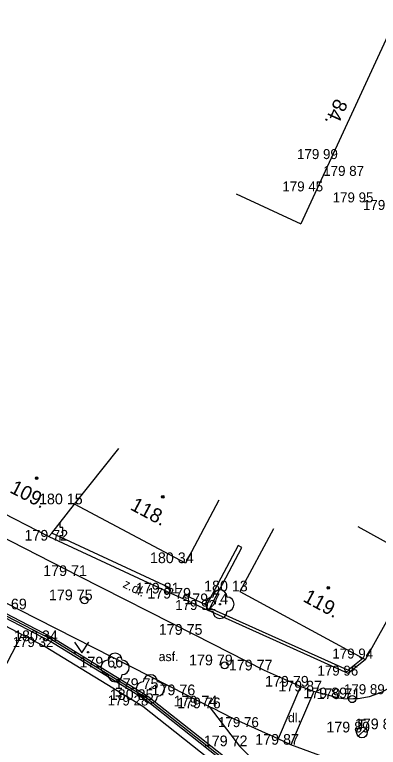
# Model space of a CAD drawing. Extents: x -537755 to -537431, y -1180722 to -1180510.
# Drawn here: x -537671.4 to -537645.9, y -1180566.9 to -1180515.4 of the extents above; entities that cross this region are included whole.
import ezdxf

# ---------------------------------------------------------------- set-up
doc = ezdxf.new("R2010")
doc.units = 0
for name, color, linetype in [('Vrstva 1', 7, 'Continuous'), ('Vrstva 10', 7, 'Continuous'), ('Vrstva 11', 7, 'Continuous'), ('Vrstva 15', 7, 'Continuous'), ('Vrstva 22', 7, 'Continuous'), ('Vrstva 24', 7, 'Continuous'), ('Vrstva 28', 7, 'Continuous'), ('Vrstva 3', 7, 'Continuous'), ('Vrstva 31', 7, 'Continuous'), ('Vrstva 36', 7, 'Continuous'), ('Vrstva 39', 7, 'Continuous'), ('Vrstva 40', 7, 'Continuous'), ('Vrstva 47', 7, 'Continuous'), ('Vrstva 5', 7, 'Continuous'), ('Vrstva 7', 7, 'Continuous'), ('Vrstva 8', 7, 'Continuous'), ('Vrstva 9', 7, 'Continuous')]:
    doc.layers.add(name, color=color, linetype=linetype)

msp = doc.modelspace()

# ---------------------------------------------------------------- linework, layer by layer
at = {"layer": 'Vrstva 1'}
for p, q in [((-537649.27, -1180525.57), (-537649.27, -1180525.57)), ((-537647.43, -1180526.75), (-537647.43, -1180526.75)), ((-537650.3, -1180527.84), (-537650.3, -1180527.84)), ((-537646.77, -1180528.61), (-537646.77, -1180528.61)), ((-537667.22, -1180549.8), (-537667.22, -1180549.8)), ((-537669.02, -1180552.06), (-537669.02, -1180552.06)), ((-537668.24, -1180552.35), (-537668.24, -1180552.35)), ((-537669.88, -1180553.41), (-537669.88, -1180553.41)), ((-537659.43, -1180553.93), (-537659.43, -1180553.93)), ((-537666.926, -1180554.833), (-537666.926, -1180554.833)), ((-537660.42, -1180556.06), (-537660.42, -1180556.06)), ((-537655.63, -1180555.91), (-537655.63, -1180555.91)), ((-537666.524, -1180556.535), (-537666.524, -1180556.535)), ((-537659.62, -1180556.42), (-537659.62, -1180556.42)), ((-537671.36, -1180557.05), (-537671.36, -1180557.05)), ((-537657.02, -1180556.81), (-537657.02, -1180556.81)), ((-537671.146, -1180557.174), (-537671.146, -1180557.174)), ((-537657.827, -1180557.22), (-537657.827, -1180557.22)), ((-537657.82, -1180557.26), (-537657.82, -1180557.26)), ((-537658.809, -1180558.957), (-537658.809, -1180558.957)), ((-537668.968, -1180559.405), (-537668.968, -1180559.405)), ((-537668.96, -1180559.45), (-537668.96, -1180559.45)), ((-537669.239, -1180559.818), (-537669.239, -1180559.818)), ((-537646.794, -1180560.624), (-537646.794, -1180560.624)), ((-537646.79, -1180560.7), (-537646.79, -1180560.7)), ((-537664.38, -1180561.25), (-537664.38, -1180561.25)), ((-537656.686, -1180561.103), (-537656.686, -1180561.103)), ((-537653.893, -1180561.458), (-537653.893, -1180561.458)), ((-537648.02, -1180561.67), (-537648.02, -1180561.67)), ((-537647.839, -1180561.823), (-537647.839, -1180561.823)), ((-537661.9, -1180562.76), (-537661.9, -1180562.76)), ((-537651.35, -1180562.597), (-537651.35, -1180562.597)), ((-537659.317, -1180563.201), (-537659.317, -1180563.201)), ((-537659.22, -1180563.09), (-537659.22, -1180563.09)), ((-537650.419, -1180562.937), (-537650.419, -1180562.937)), ((-537645.979, -1180563.127), (-537645.979, -1180563.127)), ((-537662.25, -1180563.533), (-537662.25, -1180563.533)), ((-537662.24, -1180563.54), (-537662.24, -1180563.54)), ((-537648.663, -1180563.416), (-537648.663, -1180563.416)), ((-537647.73, -1180563.47), (-537647.73, -1180563.47)), ((-537662.571, -1180563.919), (-537662.571, -1180563.919)), ((-537657.77, -1180563.99), (-537657.77, -1180563.99)), ((-537657.526, -1180564.116), (-537657.526, -1180564.116)), ((-537654.816, -1180565.439), (-537654.816, -1180565.439)), ((-537647.047, -1180565.81), (-537647.047, -1180565.81)), ((-537647.07, -1180565.97), (-537647.07, -1180565.97)), ((-537655.65, -1180566.78), (-537655.65, -1180566.78)), ((-537652.04, -1180566.674), (-537652.04, -1180566.674)), ((-537651.93, -1180566.61), (-537651.93, -1180566.61))]:
    msp.add_line(p, q, dxfattribs=at)
at = {"layer": 'Vrstva 10'}
for p, q in [((-537666.926, -1180554.833), (-537679.632, -1180548.341)), ((-537678.923, -1180553.196), (-537671.146, -1180557.174)), ((-537658.809, -1180558.957), (-537666.926, -1180554.833)), ((-537671.146, -1180557.174), (-537659.317, -1180563.201)), ((-537653.893, -1180561.458), (-537658.809, -1180558.957)), ((-537651.35, -1180562.597), (-537653.893, -1180561.458)), ((-537651.35, -1180562.597), (-537652.941, -1180566.264)), ((-537650.419, -1180562.937), (-537652.04, -1180566.674)), ((-537646.433, -1180568.727), (-537652.04, -1180566.674))]:
    msp.add_line(p, q, dxfattribs=at)
for points in [[(-537643.199, -1180560.493), (-537643.645, -1180561.278), (-537644.223, -1180561.973), (-537644.914, -1180562.555), (-537645.697, -1180563.006), (-537646.547, -1180563.313), (-537647.438, -1180563.465), (-537648.341, -1180563.458), (-537648.663, -1180563.416)], [(-537648.663, -1180563.416), (-537650.245, -1180562.994), (-537650.419, -1180562.937), (-537651.35, -1180562.597)], [(-537659.317, -1180563.201), (-537657.77, -1180563.99)], [(-537657.77, -1180563.99), (-537657.526, -1180564.116)], [(-537652.04, -1180566.674), (-537652.941, -1180566.264), (-537656.153, -1180564.801), (-537657.526, -1180564.116)]]:
    msp.add_lwpolyline(points, dxfattribs=at)
at = {"layer": 'Vrstva 11'}
msp.add_lwpolyline([(-537657.77, -1180563.99), (-537655.65, -1180566.78), (-537652.35, -1180570.03)], dxfattribs=at)
at = {"layer": 'Vrstva 15'}
msp.add_line((-537674.016, -1180564.877), (-537670.932, -1180558.939), dxfattribs=at)
at = {"layer": 'Vrstva 22'}
for centre in [(-537657.02, -1180556.81), (-537664.38, -1180561.25), (-537661.9, -1180562.76)]:
    msp.add_circle(centre, 0.05, dxfattribs=at)
for centre, start, end in [((-537657.02, -1180556.31), 0, 180), ((-537657.52, -1180556.81), 90, 270), ((-537656.52, -1180556.81), 270, 90), ((-537657.02, -1180557.31), 180, 0), ((-537664.38, -1180560.75), 0, 180), ((-537664.88, -1180561.25), 90, 270), ((-537663.88, -1180561.25), 270, 90), ((-537664.38, -1180561.75), 180, 0), ((-537661.9, -1180562.26), 0, 180), ((-537662.4, -1180562.76), 90, 270), ((-537661.4, -1180562.76), 270, 90), ((-537661.9, -1180563.26), 180, 0)]:
    msp.add_arc(centre, 0.5, start, end, dxfattribs=at)
at = {"layer": 'Vrstva 24'}
for p, q in [((-537668.24, -1180551.429), (-537668.24, -1180551.061)), ((-537668.057, -1180551.431), (-537668.24, -1180551.429)), ((-537668.057, -1180551.983), (-537668.057, -1180551.431)), ((-537668.24, -1180552.35), (-537668.24, -1180551.983)), ((-537668.24, -1180551.983), (-537668.057, -1180551.983))]:
    msp.add_line(p, q, dxfattribs=at)
at = {"layer": 'Vrstva 28'}
for p, q in [((-537647.297, -1180564.935), (-537646.797, -1180564.935)), ((-537647.047, -1180565.435), (-537647.047, -1180564.935)), ((-537647.305, -1180566.082), (-537646.775, -1180565.552))]:
    msp.add_line(p, q, dxfattribs=at)
for centre, radius in [((-537666.524, -1180556.535), 0.25), ((-537656.686, -1180561.103), 0.25), ((-537647.047, -1180565.81), 0.375)]:
    msp.add_circle(centre, radius, dxfattribs=at)
at = {"layer": 'Vrstva 31'}
msp.add_circle((-537647.73, -1180563.47), 0.25, dxfattribs=at)
at = {"layer": 'Vrstva 36'}
msp.add_lwpolyline([(-537667.223, -1180559.486), (-537666.723, -1180560.236), (-537666.223, -1180559.486)], dxfattribs=at)
for centre in [(-537667.173, -1180560.186), (-537666.274, -1180560.186)]:
    msp.add_circle(centre, 0.05, dxfattribs=at)
at = {"layer": 'Vrstva 39'}
for centre, radius in [((-537669.885, -1180547.966), 0.09), ((-537669.885, -1180547.966), 0.0398), ((-537661.034, -1180549.278), 0.09), ((-537661.034, -1180549.278), 0.0398), ((-537649.41, -1180555.66), 0.09), ((-537649.41, -1180555.66), 0.0398)]:
    msp.add_circle(centre, radius, dxfattribs=at)
at = {"layer": 'Vrstva 5'}
for p, q in [((-537644.571, -1180515.434), (-537651.348, -1180530.109)), ((-537655.887, -1180528.013), (-537651.348, -1180530.109)), ((-537667.22, -1180549.8), (-537664.104, -1180545.888)), ((-537668.828, -1180551.819), (-537667.22, -1180549.8)), ((-537659.43, -1180553.93), (-537667.22, -1180549.8)), ((-537657.088, -1180549.512), (-537659.43, -1180553.93)), ((-537647.333, -1180551.366), (-537643.178, -1180553.669)), ((-537669.02, -1180552.06), (-537668.828, -1180551.819)), ((-537653.248, -1180551.514), (-537655.63, -1180555.91)), ((-537655.63, -1180555.91), (-537646.982, -1180560.596)), ((-537646.982, -1180560.596), (-537646.79, -1180560.7))]:
    msp.add_line(p, q, dxfattribs=at)
for points in [[(-537673.06, -1180550), (-537669.02, -1180552.06)], [(-537646.79, -1180560.7), (-537644.596, -1180556.742)]]:
    msp.add_lwpolyline(points, dxfattribs=at)
at = {"layer": 'Vrstva 7'}
for p, q in [((-537669.02, -1180552.06), (-537660.42, -1180556.06)), ((-537655.739, -1180552.691), (-537657.952, -1180556.868)), ((-537668.82, -1180559.144), (-537675.938, -1180555.447)), ((-537668.968, -1180559.405), (-537676.072, -1180555.716)), ((-537669.289, -1180559.792), (-537675.712, -1180556.456)), ((-537659.62, -1180556.42), (-537657.82, -1180557.26)), ((-537648.049, -1180561.438), (-537657.726, -1180557.083)), ((-537648.02, -1180561.67), (-537657.82, -1180557.26)), ((-537662.078, -1180563.287), (-537668.82, -1180559.144)), ((-537662.25, -1180563.533), (-537668.968, -1180559.405)), ((-537662.438, -1180564.001), (-537669.289, -1180559.792)), ((-537648.049, -1180561.438), (-537646.982, -1180560.596)), ((-537646.79, -1180560.7), (-537648.02, -1180561.67)), ((-537655.765, -1180568.26), (-537662.078, -1180563.287)), ((-537655.956, -1180568.491), (-537662.25, -1180563.533)), ((-537656.266, -1180568.863), (-537662.438, -1180564.001))]:
    msp.add_line(p, q, dxfattribs=at)
for points in [[(-537660.291, -1180555.782), (-537668.828, -1180551.819)], [(-537657.82, -1180557.26), (-537657.726, -1180557.083), (-537655.474, -1180552.831), (-537655.739, -1180552.691)], [(-537660.42, -1180556.06), (-537660.291, -1180555.782)], [(-537657.952, -1180556.868), (-537659.495, -1180556.152), (-537659.62, -1180556.42)]]:
    msp.add_lwpolyline(points, dxfattribs=at)
at = {"layer": 'Vrstva 8'}
msp.add_line((-537660.42, -1180556.06), (-537659.62, -1180556.42), dxfattribs=at)
at = {"layer": 'Vrstva 9'}
for p, q in [((-537668.894, -1180559.274), (-537676.005, -1180555.582)), ((-537662.164, -1180563.41), (-537668.894, -1180559.274)), ((-537655.861, -1180568.375), (-537662.164, -1180563.41))]:
    msp.add_line(p, q, dxfattribs=at)

# ---------------------------------------------------------------- texts
at = {"layer": 'Vrstva 3'}
for s, height, p in [('179 99 ', 0.7, (-537651.604, -1180525.57)), ('179 87 ', 0.7, (-537649.764, -1180526.75)), ('179 45 ', 0.7, (-537652.634, -1180527.84)), ('179 95 ', 0.7, (-537649.104, -1180528.61)), ('179 88 ', 0.7, (-537646.974, -1180529.14)), ('180 15 ', 0.75, (-537669.72, -1180549.8)), ('179 72 ', 0.75, (-537670.74, -1180552.35)), ('180 34 ', 0.75, (-537661.93, -1180553.93)), ('179 71 ', 0.75, (-537669.426, -1180554.833)), ('179 81 ', 0.75, (-537662.92, -1180556.06)), ('180 13 ', 0.75, (-537658.13, -1180555.91)), ('179 75 ', 0.75, (-537669.024, -1180556.535)), ('179 79 ', 0.75, (-537662.12, -1180556.42)), ('179 74 ', 0.75, (-537659.52, -1180556.81)), ('179 69 ', 0.75, (-537673.646, -1180557.174)), ('179 92 ', 0.7, (-537660.16, -1180557.22)), ('180 34 ', 0.75, (-537671.468, -1180559.405)), ('179 75 ', 0.75, (-537661.309, -1180558.957)), ('179 32 ', 0.7, (-537671.572, -1180559.818)), ('179 94 ', 0.7, (-537649.127, -1180560.624)), ('179 66 ', 0.75, (-537666.88, -1180561.25)), ('179 79 ', 0.75, (-537659.186, -1180561.103)), ('179 77 ', 0.75, (-537656.393, -1180561.458)), ('179 96 ', 0.7, (-537650.172, -1180561.823)), ('179 75 ', 0.75, (-537664.4, -1180562.76)), ('179 79 ', 0.75, (-537653.85, -1180562.597)), ('179 87 ', 0.75, (-537652.919, -1180562.937)), ('180 35 ', 0.75, (-537664.75, -1180563.533)), ('179 76 ', 0.75, (-537661.817, -1180563.201)), ('179 89 ', 0.75, (-537651.163, -1180563.416)), ('179 71 ', 0.75, (-537650.23, -1180563.47)), ('179 89 ', 0.7, (-537648.312, -1180563.127)), ('179 28 ', 0.7, (-537664.904, -1180563.919)), ('179 74 ', 0.75, (-537660.27, -1180563.99)), ('179 76 ', 0.75, (-537660.026, -1180564.116)), ('179 76 ', 0.7, (-537657.149, -1180565.439)), ('179 89 ', 0.75, (-537647.547, -1180565.588)), ('179 89 ', 0.75, (-537649.547, -1180565.81)), ('179 72 ', 0.75, (-537658.15, -1180566.78)), ('179 87 ', 0.75, (-537654.54, -1180566.674))]:
    msp.add_text(s, height=height, dxfattribs=at).set_placement(p)
at = {"layer": 'Vrstva 40'}
msp.add_text('z.dl.', height=0.65, rotation=333.0663, dxfattribs=at).set_placement((-537663.885, -1180555.593))
for s, p in [('asf.', (-537661.323, -1180560.806)), ('dl.', (-537652.245, -1180565.098))]:
    msp.add_text(s, height=0.65, dxfattribs=at).set_placement(p)
at = {"layer": 'Vrstva 47'}
for s, rotation, p in [('84.', 245.2122, (-537648.913, -1180521.257)), ('109.', 332.9672, (-537671.837, -1180548.939)), ('118.', 332.0689, (-537663.38, -1180550.138)), ('119.', 331.5487, (-537651.253, -1180556.575))]:
    msp.add_text(s, height=1, rotation=rotation, dxfattribs=at).set_placement(p)

doc.saveas('drawing.dxf')
